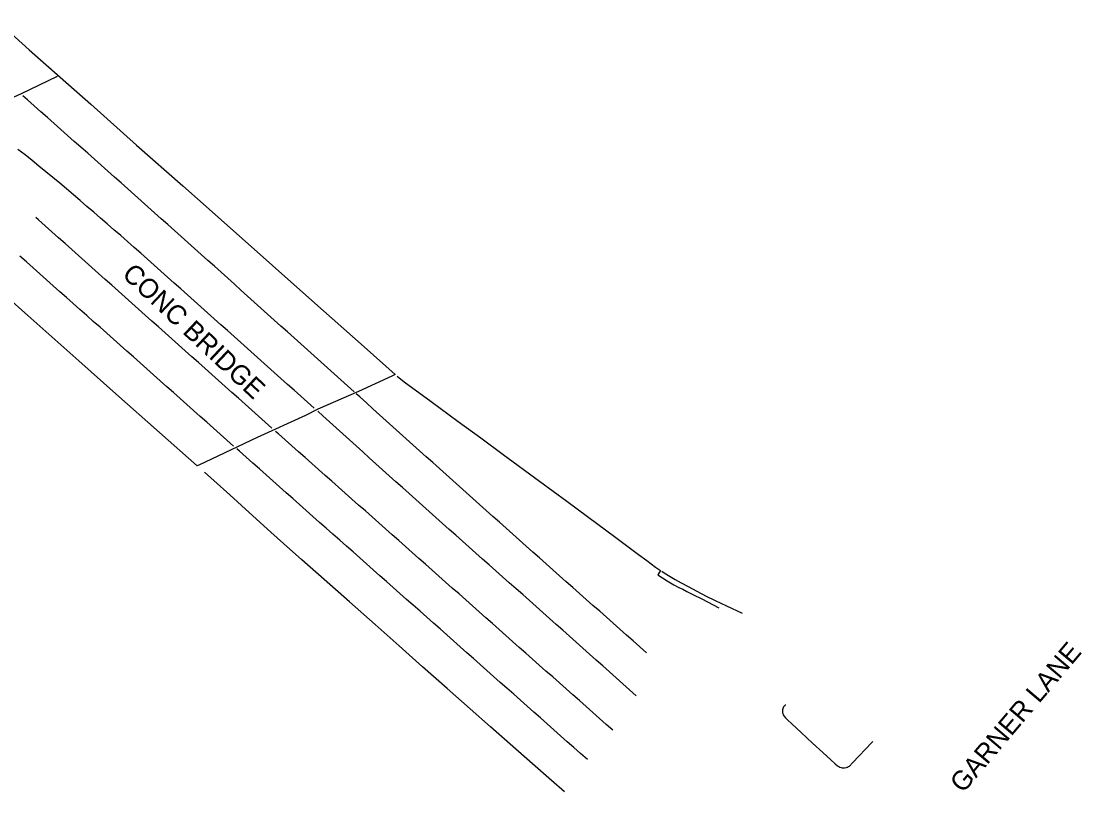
# Model space of a CAD drawing. Extents: x 1970211 to 1973046, y 801032 to 804001.
# Drawn here: x 1971628.9 to 1971925.5, y 802465.4 to 802680.9 of the extents above; entities that cross this region are included whole.
import ezdxf

# ---------------------------------------------------------------- set-up
doc = ezdxf.new("R2010")
doc.units = 0
for name, color, linetype in [('RD_EX_Bridge', 7, 'Continuous'), ('RD_EX_Bridge_Seam', 7, 'Continuous'), ('RD_EX_Conc', 7, 'Continuous'), ('RD_EX_Road', 7, 'Continuous'), ('RD_EX_Road_Paint', 7, 'Continuous'), ('RD_TX_RoadID', 7, 'Continuous')]:
    doc.layers.add(name, color=color, linetype=linetype)

msp = doc.modelspace()

# ---------------------------------------------------------------- linework, layer by layer
at = {"layer": 'RD_EX_Bridge'}
msp.add_lwpolyline([(1971622.19, 802680.91), (1971631.17, 802672.94), (1971639.77, 802665.28), (1971648.37, 802657.69), (1971661.2, 802646.29), (1971674.12, 802634.89), (1971682.29, 802627.59), (1971699.23, 802612.59), (1971710.21, 802602.8), (1971724.84, 802589.82), (1971733.52, 802582.11), (1971732.58, 802581.68), (1971723.21, 802577.36), (1971711.84, 802572.46), (1971708.41, 802570.64), (1971694.92, 802564.46), (1971682.15, 802558.44), (1971678.82, 802556.89), (1971678.12, 802556.56), (1971667.59, 802565.91), (1971655.39, 802576.71), (1971645.05, 802585.96), (1971630.72, 802598.58), (1971612.51, 802614.79)], dxfattribs=at)
at = {"layer": 'RD_EX_Bridge_Seam'}
msp.add_lwpolyline([(1971584.66, 802640.4), (1971611.14, 802652.5), (1971618.12, 802655.75), (1971629.02, 802660.65), (1971639.02, 802665.54)], dxfattribs=at)
at = {"layer": 'RD_EX_Conc'}
for points in [[(1971808.05, 802527.12), (1971808.47, 802526.86), (1971809.93, 802525.96), (1971811.79, 802524.84), (1971813.51, 802523.85), (1971815.42, 802522.8), (1971817.85, 802521.52), (1971820.49, 802520.16), (1971823.02, 802518.9), (1971826.14, 802517.43), (1971830.55, 802515.43)], [(1971842.73, 802489.69), (1971842.59, 802489.62), (1971842.47, 802489.54), (1971842.3, 802489.36), (1971842.15, 802489.15), (1971842.03, 802488.91), (1971841.94, 802488.63), (1971841.87, 802488.32), (1971841.83, 802487.98), (1971841.83, 802487.64), (1971841.89, 802487.3), (1971842.01, 802486.99), (1971842.2, 802486.69), (1971842.68, 802486.12), (1971843.22, 802485.57), (1971844.48, 802484.4), (1971847.09, 802481.98), (1971850.23, 802479.07), (1971853.11, 802476.42), (1971855.34, 802474.38), (1971856.55, 802473.27), (1971857.23, 802472.72), (1971857.57, 802472.51), (1971857.89, 802472.34), (1971858.21, 802472.22), (1971858.53, 802472.15), (1971858.85, 802472.12), (1971859.17, 802472.14), (1971859.72, 802472.23), (1971859.93, 802472.29), (1971860.09, 802472.36), (1971860.33, 802472.5), (1971860.55, 802472.64), (1971861.4, 802473.49), (1971866.89, 802479.32), (1971867.06, 802479.51)]]:
    msp.add_lwpolyline(points, dxfattribs=at)
at = {"layer": 'RD_EX_Road'}
for points in [[(1971734.03, 802581.68), (1971736.06, 802580.07), (1971743.6, 802574.55), (1971751.14, 802569.02), (1971757.44, 802564.39), (1971763.74, 802559.77), (1971773.85, 802552.34), (1971781.48, 802546.73), (1971787.27, 802542.46), (1971795.24, 802536.55), (1971798.94, 802533.76), (1971801.6, 802531.76), (1971803.85, 802530.07), (1971806.35, 802528.29), (1971807.73, 802527.33), (1971806.94, 802526.08), (1971809.54, 802524.47), (1971811.47, 802523.35), (1971812.88, 802522.59), (1971813.92, 802522.05), (1971815.1, 802521.45), (1971816.94, 802520.51), (1971819.26, 802519.35), (1971824.07, 802516.88)], [(1971780.84, 802465.44), (1971777.19, 802468.56), (1971771.92, 802473.22), (1971765.66, 802478.75), (1971760.12, 802483.64), (1971754.51, 802488.6), (1971748, 802494.36), (1971741.17, 802500.42), (1971734.59, 802506.28), (1971727.9, 802512.24), (1971720.7, 802518.59), (1971713.65, 802524.81), (1971707.4, 802530.34), (1971702.31, 802534.87), (1971698.73, 802538.08), (1971692.68, 802543.52), (1971687.22, 802548.43), (1971680.15, 802554.78)]]:
    msp.add_lwpolyline(points, dxfattribs=at)
at = {"layer": 'RD_EX_Road_Paint'}
for points in [[(1971721.99, 802577.29), (1971720.14, 802578.97), (1971718.29, 802580.65), (1971716.43, 802582.33), (1971714.57, 802583.99), (1971712.71, 802585.66), (1971710.85, 802587.33), (1971708.99, 802589), (1971707.13, 802590.67), (1971705.27, 802592.34), (1971703.41, 802594.01), (1971701.55, 802595.68), (1971699.69, 802597.35), (1971697.82, 802599.02), (1971695.96, 802600.69), (1971694.1, 802602.35), (1971692.24, 802604.02), (1971690.38, 802605.69), (1971688.52, 802607.36), (1971686.66, 802609.03), (1971684.8, 802610.7), (1971682.94, 802612.37), (1971681.07, 802614.04), (1971679.21, 802615.7), (1971677.34, 802617.37), (1971675.48, 802619.03), (1971673.62, 802620.7), (1971671.75, 802622.36), (1971669.89, 802624.03), (1971668.02, 802625.69), (1971666.16, 802627.35), (1971664.29, 802629.02), (1971662.43, 802630.68), (1971660.56, 802632.35), (1971658.7, 802634.01), (1971656.83, 802635.68), (1971654.97, 802637.34), (1971653.11, 802639.01), (1971651.24, 802640.67), (1971649.37, 802642.34), (1971647.5, 802644), (1971645.63, 802645.65), (1971643.76, 802647.31), (1971641.89, 802648.97), (1971640.02, 802650.63), (1971638.15, 802652.29), (1971636.28, 802653.94), (1971634.41, 802655.6), (1971632.54, 802657.26), (1971630.67, 802658.92), (1971629.4, 802660.05)], [(1971710.83, 802572.69), (1971708.97, 802574.36), (1971707.11, 802576.03), (1971705.25, 802577.7), (1971703.39, 802579.36), (1971701.53, 802581.03), (1971699.67, 802582.7), (1971697.8, 802584.37), (1971695.94, 802586.04), (1971694.08, 802587.71), (1971692.22, 802589.38), (1971690.36, 802591.05), (1971688.5, 802592.71), (1971686.64, 802594.38), (1971684.77, 802596.05), (1971682.91, 802597.72), (1971681.05, 802599.38), (1971679.18, 802601.05), (1971677.31, 802602.71), (1971675.45, 802604.37), (1971673.58, 802606.03), (1971671.72, 802607.7), (1971669.85, 802609.36), (1971667.98, 802611.02), (1971666.12, 802612.69), (1971664.25, 802614.35), (1971662.38, 802616.01), (1971660.5, 802617.66), (1971658.62, 802619.3), (1971656.74, 802620.95), (1971654.86, 802622.6), (1971652.98, 802624.24), (1971651.09, 802625.88), (1971649.19, 802627.51), (1971647.3, 802629.14), (1971645.4, 802630.77), (1971643.5, 802632.39), (1971641.61, 802634.02), (1971639.68, 802635.61), (1971637.75, 802637.2), (1971635.81, 802638.78), (1971633.88, 802640.36), (1971631.94, 802641.94), (1971629.99, 802643.5), (1971628, 802645.02)], [(1971699.02, 802567.14), (1971697.16, 802568.8), (1971695.29, 802570.46), (1971693.43, 802572.13), (1971691.56, 802573.79), (1971689.7, 802575.46), (1971687.83, 802577.12), (1971685.96, 802578.78), (1971684.1, 802580.45), (1971682.23, 802582.11), (1971680.37, 802583.77), (1971678.5, 802585.44), (1971676.64, 802587.1), (1971674.77, 802588.76), (1971672.9, 802590.43), (1971671.04, 802592.09), (1971669.17, 802593.76), (1971667.31, 802595.42), (1971665.44, 802597.08), (1971663.58, 802598.75), (1971661.71, 802600.41), (1971659.84, 802602.07), (1971657.98, 802603.74), (1971656.11, 802605.4), (1971654.25, 802607.06), (1971652.38, 802608.73), (1971650.52, 802610.39), (1971648.65, 802612.06), (1971646.78, 802613.72), (1971644.92, 802615.38), (1971643.05, 802617.05), (1971641.19, 802618.71), (1971639.32, 802620.37), (1971637.46, 802622.04), (1971635.59, 802623.7), (1971633.72, 802625.36), (1971632.99, 802626.02)], [(1971688.32, 802562.11), (1971686.45, 802563.77), (1971684.58, 802565.43), (1971682.72, 802567.09), (1971680.85, 802568.75), (1971678.98, 802570.41), (1971677.11, 802572.07), (1971675.24, 802573.73), (1971673.37, 802575.39), (1971671.51, 802577.05), (1971669.64, 802578.71), (1971667.77, 802580.37), (1971665.9, 802582.03), (1971664.03, 802583.69), (1971662.16, 802585.35), (1971660.29, 802587.02), (1971658.43, 802588.68), (1971656.56, 802590.34), (1971654.69, 802592), (1971652.82, 802593.66), (1971650.95, 802595.32), (1971649.08, 802596.98), (1971647.22, 802598.64), (1971645.35, 802600.3), (1971643.48, 802601.96), (1971641.61, 802603.62), (1971639.74, 802605.28), (1971637.87, 802606.94), (1971636, 802608.6), (1971634.14, 802610.26), (1971632.27, 802611.92), (1971630.4, 802613.58), (1971628.53, 802615.24)], [(1971803.8, 802504.3), (1971801.93, 802505.95), (1971800.06, 802507.61), (1971798.19, 802509.27), (1971796.31, 802510.93), (1971794.44, 802512.58), (1971792.57, 802514.24), (1971790.7, 802515.9), (1971788.83, 802517.56), (1971786.96, 802519.21), (1971785.09, 802520.87), (1971783.21, 802522.53), (1971781.34, 802524.19), (1971779.47, 802525.84), (1971777.6, 802527.5), (1971775.73, 802529.16), (1971773.86, 802530.82), (1971771.99, 802532.47), (1971770.11, 802534.13), (1971768.24, 802535.79), (1971766.38, 802537.46), (1971764.52, 802539.13), (1971762.66, 802540.79), (1971760.8, 802542.46), (1971758.94, 802544.13), (1971757.07, 802545.8), (1971755.21, 802547.47), (1971753.35, 802549.13), (1971751.49, 802550.8), (1971749.63, 802552.47), (1971747.76, 802554.14), (1971745.9, 802555.81), (1971744.04, 802557.47), (1971742.18, 802559.14), (1971740.32, 802560.81), (1971738.46, 802562.48), (1971736.6, 802564.15), (1971734.74, 802565.82), (1971732.88, 802567.49), (1971731.02, 802569.17), (1971729.16, 802570.84), (1971727.3, 802572.51), (1971725.44, 802574.18), (1971723.58, 802575.85), (1971722.61, 802576.72)], [(1971800.91, 802492.31), (1971799.05, 802493.97), (1971797.18, 802495.63), (1971795.31, 802497.29), (1971793.45, 802498.96), (1971791.58, 802500.62), (1971789.71, 802502.28), (1971787.85, 802503.94), (1971785.98, 802505.61), (1971784.11, 802507.27), (1971782.24, 802508.93), (1971780.38, 802510.59), (1971778.51, 802512.26), (1971776.64, 802513.92), (1971774.78, 802515.58), (1971772.91, 802517.24), (1971771.04, 802518.91), (1971769.17, 802520.56), (1971767.3, 802522.22), (1971765.43, 802523.88), (1971763.56, 802525.54), (1971761.69, 802527.2), (1971759.82, 802528.86), (1971757.95, 802530.52), (1971756.09, 802532.18), (1971754.22, 802533.84), (1971752.35, 802535.5), (1971750.48, 802537.16), (1971748.61, 802538.82), (1971746.74, 802540.48), (1971744.87, 802542.14), (1971743, 802543.8), (1971741.13, 802545.46), (1971739.27, 802547.13), (1971737.41, 802548.81), (1971735.56, 802550.48), (1971733.7, 802552.15), (1971731.84, 802553.83), (1971729.99, 802555.5), (1971728.13, 802557.17), (1971726.27, 802558.85), (1971724.42, 802560.52), (1971722.56, 802562.2), (1971720.7, 802563.87), (1971718.85, 802565.54), (1971716.99, 802567.22), (1971715.13, 802568.89), (1971713.28, 802570.56), (1971711.85, 802571.85)], [(1971794.4, 802482.63), (1971792.53, 802484.29), (1971790.66, 802485.94), (1971788.79, 802487.6), (1971786.91, 802489.26), (1971785.04, 802490.92), (1971783.17, 802492.57), (1971781.3, 802494.23), (1971779.43, 802495.89), (1971777.56, 802497.55), (1971775.68, 802499.2), (1971773.81, 802500.86), (1971771.94, 802502.52), (1971770.07, 802504.18), (1971768.2, 802505.83), (1971766.33, 802507.49), (1971764.46, 802509.15), (1971762.58, 802510.81), (1971760.71, 802512.46), (1971758.84, 802514.12), (1971756.97, 802515.78), (1971755.1, 802517.44), (1971753.23, 802519.09), (1971751.36, 802520.75), (1971749.49, 802522.41), (1971747.62, 802524.07), (1971745.75, 802525.73), (1971743.87, 802527.38), (1971742, 802529.04), (1971740.13, 802530.7), (1971738.26, 802532.36), (1971736.39, 802534.02), (1971734.52, 802535.67), (1971732.65, 802537.33), (1971730.78, 802538.99), (1971728.91, 802540.65), (1971727.04, 802542.31), (1971725.17, 802543.96), (1971723.29, 802545.62), (1971721.42, 802547.28), (1971719.55, 802548.94), (1971717.68, 802550.6), (1971715.81, 802552.25), (1971713.94, 802553.91), (1971712.07, 802555.57), (1971710.2, 802557.23), (1971708.33, 802558.89), (1971706.46, 802560.54), (1971704.58, 802562.2), (1971702.71, 802563.86), (1971700.84, 802565.52), (1971700.06, 802566.21)], [(1971787.26, 802474.51), (1971785.38, 802476.16), (1971783.5, 802477.81), (1971781.62, 802479.45), (1971779.74, 802481.1), (1971777.87, 802482.76), (1971776, 802484.42), (1971774.13, 802486.08), (1971772.26, 802487.74), (1971770.39, 802489.4), (1971768.52, 802491.06), (1971766.65, 802492.72), (1971764.78, 802494.38), (1971762.91, 802496.04), (1971761.04, 802497.7), (1971759.17, 802499.35), (1971757.3, 802501.01), (1971755.43, 802502.67), (1971753.56, 802504.33), (1971751.69, 802505.99), (1971749.82, 802507.65), (1971747.94, 802509.3), (1971746.07, 802510.96), (1971744.2, 802512.61), (1971742.32, 802514.27), (1971740.45, 802515.93), (1971738.58, 802517.58), (1971736.71, 802519.24), (1971734.83, 802520.89), (1971732.96, 802522.55), (1971731.09, 802524.21), (1971729.22, 802525.86), (1971727.34, 802527.52), (1971725.47, 802529.17), (1971723.6, 802530.83), (1971721.72, 802532.49), (1971719.85, 802534.14), (1971717.98, 802535.8), (1971716.11, 802537.46), (1971714.24, 802539.12), (1971712.37, 802540.77), (1971710.5, 802542.43), (1971708.63, 802544.09), (1971706.76, 802545.75), (1971704.89, 802547.41), (1971703.02, 802549.07), (1971701.15, 802550.72), (1971699.28, 802552.38), (1971697.41, 802554.04), (1971695.54, 802555.7), (1971693.66, 802557.36), (1971691.79, 802559.02), (1971689.92, 802560.68), (1971689.21, 802561.31)]]:
    msp.add_lwpolyline(points, dxfattribs=at)

# ---------------------------------------------------------------- texts
at = {"layer": 'RD_TX_RoadID'}
for s, rotation, p in [('CONC BRIDGE', 316.8085, (1971656.83, 802609.75)), ('GARNER LANE', 49.7937, (1971892.33, 802464.84))]:
    msp.add_text(s, height=5.4, rotation=rotation, dxfattribs=at).set_placement(p)

doc.saveas('drawing.dxf')
